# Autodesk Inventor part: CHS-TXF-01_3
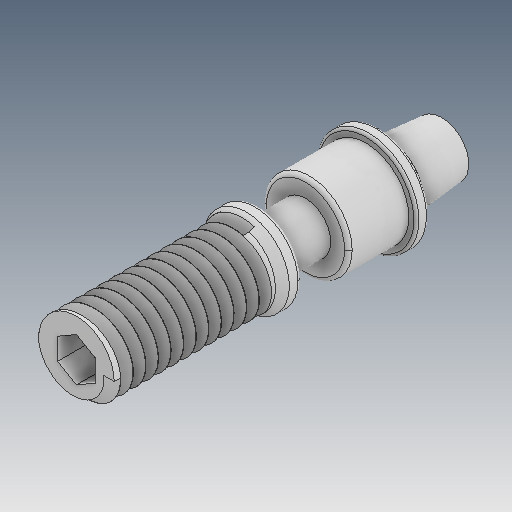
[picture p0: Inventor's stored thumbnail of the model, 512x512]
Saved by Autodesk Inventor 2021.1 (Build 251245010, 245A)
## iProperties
Created: 2021-05
Part Number: CHS-TXF-01_3
Material: Ogólny
Document SubType Name: Modeling
Designer: user
Density: 1 g/cm^3
Appearance: Domyślna
Author: user
Revision Number: ÈÎºÎ
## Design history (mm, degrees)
feature "ÊäÈë1"
node "Bryła1"
